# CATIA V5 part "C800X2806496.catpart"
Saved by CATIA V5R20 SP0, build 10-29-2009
Part number: C800X2806496
Source: Unknown
Property "A": "90"
Property "ARTICLENO": "C800X2806496"
Property "B": "45"
Property "BOMINFO": "C800X2806496"
Property "C": "124"
Property "CA": "C800X2806496"
Property "D1": "170"
Property "DES": "ROTATING EYEBOLT WITH RING Ton 28,0 M64x96"
Property "E": "165"
Property "H": "333"
Property "L": "96"
Property "LINA": "C800X2806496"
Property "NB": "C800X2806496"
Property "NBSYN": "$CODE."
Property "NN": "C800X"
Property "NT": "Rotating eyebolt with ring"
Property "SIZE": "M64"
Property "SUPPLIER": "CF"
Property "SW": "134"
Property "WEIGHT": "29000"
Property "WLL": "28.00"
Bounding box of the stored display mesh (mm): x -90 to 90, y -96 to 378, z -85 to 85
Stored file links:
  C:\Users\Utente\Desktop\3D files 800X\C800X2806496.catpart

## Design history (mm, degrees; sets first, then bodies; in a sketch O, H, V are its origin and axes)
Body1 "Geometry.1" (main body)
  Solid1 "C800X2806496.catpart": solid without history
